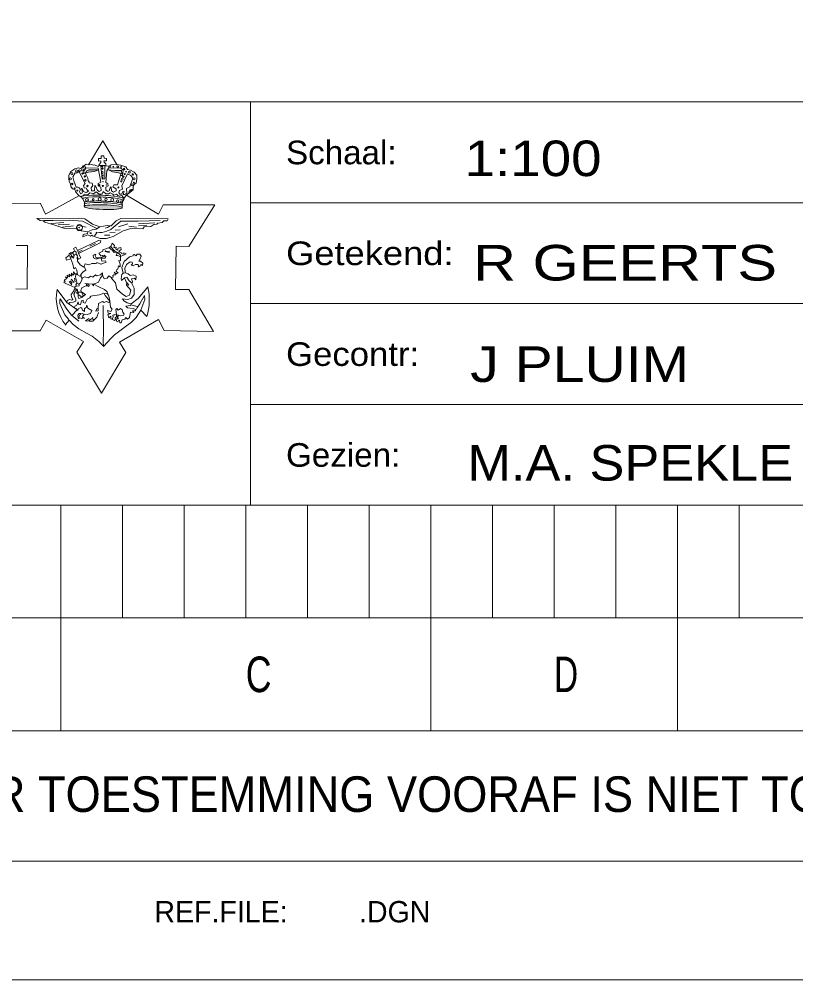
# Model space of a CAD drawing. Extents: x 295824 to 414724, y 24924 to 109024.
# Drawn here: x 402973 to 409522, y 24924 to 33022 of the extents above; entities that cross this region are included whole.
import ezdxf

# ---------------------------------------------------------------- set-up
doc = ezdxf.new("R2010")
doc.units = 0
doc.header["$LTSCALE"] = 100
doc.header["$PDMODE"] = 32
doc.header["$PDSIZE"] = 50
doc.layers.add('1', color=7, linetype='Continuous', lineweight=13)
doc.layers.add('3', color=7, linetype='Continuous')

msp = doc.modelspace()

# ---------------------------------------------------------------- hatches: boundary and pattern name
at = {"layer": '1'}
for points in [[(403531.6, 31722.8), (403540.6, 31743.8), (403560.6, 31751.8), (403641.6, 31751.8), (403609.6, 31737.8), (403557.6, 31731.8)], [(403720.6, 31751.8), (403780.6, 31745.8), (403834.6, 31745.8), (403837.6, 31716.8), (403809.6, 31727.8), (403760.6, 31733.8), (403725.6, 31750.8)]]:
    msp.add_hatch(color=256, dxfattribs=at).paths.add_polyline_path(points)
h = msp.add_hatch(color=256, dxfattribs=at)
edge = h.paths.add_edge_path()
edge.add_ellipse((403681.3, 31437.6), major_axis=(161, -5), ratio=0.122443, start_angle=0, end_angle=360)

# ---------------------------------------------------------------- linework, layer by layer
for p, q in [((395823.6, 32323.8), (413723.6, 32323.8)), ((404923.6, 32323.8), (404923.6, 28923.8)), ((403696.6, 31787.8), (403649.6, 31787.8)), ((403662.6, 31785.8), (403672.6, 31673.8)), ((403475.6, 31533.8), (403195.6, 31378.8)), ((403494.6, 31523.8), (403508.6, 31507.8)), ((403857.6, 31507.8), (403849.6, 31493.8)), ((403877.6, 31538.8), (404148.6, 31377.8)), ((403520.6, 31443.8), (403522.6, 31463.8)), ((403841.6, 31432.8), (403841.6, 31453.8)), ((404923.6, 31473.8), (413723.6, 31473.8)), ((403180.6, 31324.8), (403259.6, 31324.8)), ((403242.6, 31298.8), (403348.6, 31308.8)), ((403300.6, 31288.8), (403398.6, 31294.8)), ((403338.6, 31269.8), (403431.6, 31279.8)), ((403453.6, 31258.8), (403481.6, 31264.8)), ((403471.6, 31282.8), (403536.6, 31269.8)), ((403506.6, 31317.8), (403628.6, 31257.8)), ((403811.6, 31271.8), (403890.6, 31295.8)), ((403896.6, 31275.8), (403961.6, 31268.8)), ((403976.6, 31319.8), (404161.6, 31325.8)), ((403979.6, 31297.8), (404117.6, 31304.8)), ((403980.6, 31279.8), (404049.6, 31285.8)), ((403693.6, 31199.8), (403737.6, 31200.8)), ((403737.6, 31222.8), (403781.6, 31219.8)), ((403781.6, 31243.8), (403825.6, 31244.8)), ((403568.6, 31108.8), (403615.6, 31129.8)), ((403391.6, 31027.8), (403410.6, 31016.8)), ((403412.6, 31018.8), (403432.6, 31026.8)), ((403466.6, 31069.8), (403474.6, 31046.8)), ((403473.6, 31057.8), (403503.6, 31074.8)), ((403679.6, 31024.8), (403696.6, 31017.8)), ((403394.6, 30811.8), (403417.6, 30781.8)), ((403404.6, 30816.8), (403420.6, 30797.8)), ((403412.6, 30830.8), (403437.6, 30801.8)), ((403439.6, 30839.8), (403445.6, 30808.8)), ((403914.6, 30613.8), (403967.6, 30598.8)), ((404923.6, 30623.8), (413723.6, 30623.8)), ((403522.6, 30498.8), (403507.6, 30512.8)), ((403588.6, 30498.8), (403594.6, 30509.8)), ((404923.6, 29773.8), (413723.6, 29773.8)), ((395823.6, 28923.8), (413723.6, 28923.8)), ((403323.6, 28923.8), (403323.6, 27023.8)), ((403843.6, 28923.8), (403843.6, 27973.8)), ((404363.6, 28923.8), (404363.6, 27973.8)), ((404883.6, 28923.8), (404883.6, 27973.8)), ((405403.6, 28923.8), (405403.6, 27973.8)), ((405923.6, 28923.8), (405923.6, 27973.8)), ((406443.6, 28923.8), (406443.6, 27023.8)), ((406963.6, 28923.8), (406963.6, 27973.8)), ((407483.6, 28923.8), (407483.6, 27973.8)), ((408003.6, 28923.8), (408003.6, 27973.8)), ((408523.6, 28923.8), (408523.6, 27023.8)), ((409043.6, 28923.8), (409043.6, 27973.8)), ((413723.6, 27973.8), (399163.6, 27973.8)), ((395823.6, 27023.8), (413723.6, 27023.8)), ((304995.6, 24923.8), (414723.6, 24923.8))]:
    msp.add_line(p, q, dxfattribs=at)
for points in [[(304995.6, 25923.8), (413723.6, 25923.8), (413723.6, 108023.8), (304995.6, 108023.8)], [(403557.6, 31794.8), (403678.6, 31996.8), (403795.6, 31795.8)], [(403493.6, 31524.8), (403475.6, 31536.8), (403449.6, 31562.8), (403441.6, 31584.8), (403423.6, 31592.8), (403407.6, 31610.8), (403404.6, 31632.8), (403394.6, 31653.8), (403390.6, 31675.8), (403391.6, 31707.8), (403408.6, 31737.8), (403441.6, 31760.8), (403472.6, 31768.8), (403489.6, 31763.8), (403504.6, 31771.8), (403512.6, 31786.8), (403524.6, 31787.8), (403538.6, 31798.8), (403556.6, 31793.8), (403585.6, 31796.8), (403595.6, 31789.8), (403606.6, 31792.8), (403642.6, 31780.8), (403647.6, 31796.8), (403660.6, 31814.8), (403660.6, 31826.8), (403641.6, 31825.8), (403642.6, 31846.8), (403663.6, 31847.8), (403663.6, 31869.8), (403687.6, 31869.8), (403690.6, 31849.8), (403709.6, 31848.8), (403709.6, 31827.8), (403687.6, 31827.8), (403689.6, 31816.8), (403703.6, 31801.8), (403704.6, 31786.8), (403732.6, 31781.8), (403747.6, 31793.8)], [(403608.6, 31575.8), (403611.6, 31618.8), (403616.6, 31616.8), (403633.6, 31576.8), (403647.6, 31568.8), (403664.6, 31576.8), (403660.6, 31604.8), (403639.6, 31615.8), (403639.6, 31636.8), (403654.6, 31644.8), (403662.6, 31648.8), (403638.6, 31764.8), (403538.6, 31769.8), (403517.6, 31743.8), (403518.6, 31720.8), (403530.6, 31725.8), (403551.6, 31680.8), (403555.6, 31659.8), (403563.6, 31649.8), (403562.6, 31641.8), (403589.6, 31640.8), (403594.6, 31619.8), (403579.6, 31599.8), (403583.6, 31574.8), (403608.6, 31574.8)], [(403672.6, 31671.8), (403694.6, 31675.8), (403695.6, 31785.8), (403702.6, 31786.8)], [(403827.6, 31702.8), (403844.6, 31704.8), (403850.6, 31749.8), (403831.6, 31764.8), (403792.6, 31768.8), (403726.6, 31766.8), (403711.6, 31742.8), (403703.6, 31644.8), (403720.6, 31634.8), (403722.6, 31615.8), (403702.6, 31605.8), (403702.6, 31579.8), (403718.6, 31570.8)], [(403747.6, 31793.8), (403791.6, 31796.8), (403830.6, 31790.8)], [(403827.6, 31791.8), (403871.6, 31775.8), (403887.6, 31755.8), (403910.6, 31749.8), (403943.6, 31730.8), (403966.6, 31706.8), (403964.6, 31675.8), (403959.6, 31638.8), (403941.6, 31628.8), (403935.6, 31607.8), (403935.6, 31583.8), (403884.6, 31542.8), (403854.6, 31511.8)], [(403542.6, 31562.8), (403556.6, 31572.8), (403543.6, 31584.8), (403540.6, 31596.8), (403521.6, 31598.8), (403515.6, 31619.8), (403529.6, 31635.8), (403478.6, 31735.8), (403457.6, 31723.8), (403444.6, 31725.8), (403426.6, 31693.8), (403432.6, 31657.8), (403453.6, 31605.8), (403466.6, 31605.8), (403478.6, 31598.8), (403490.6, 31586.8), (403481.6, 31567.8), (403490.6, 31549.8), (403501.6, 31552.8), (403506.6, 31564.8), (403498.6, 31594.8), (403505.6, 31595.8), (403516.6, 31568.8), (403535.6, 31559.8), (403539.6, 31560.8)], [(403718.6, 31568.8), (403730.6, 31574.8), (403742.6, 31609.8), (403748.6, 31606.8), (403750.6, 31573.8), (403767.6, 31564.8), (403789.6, 31573.8), (403791.6, 31591.8), (403763.6, 31607.8), (403771.6, 31624.8), (403802.6, 31624.8), (403831.6, 31715.8)], [(403834.6, 31545.8), (403849.6, 31570.8), (403858.6, 31567.8), (403848.6, 31543.8), (403864.6, 31543.8), (403879.6, 31553.8), (403877.6, 31595.8), (403906.6, 31609.8), (403932.6, 31682.8), (403915.6, 31704.8), (403887.6, 31717.8), (403860.6, 31663.8), (403838.6, 31617.8), (403844.6, 31587.8), (403819.6, 31577.8), (403813.6, 31556.8), (403822.6, 31545.8), (403836.6, 31546.8)], [(403494.6, 31523.8), (403493.6, 31526.8), (403517.6, 31538.8), (403520.6, 31547.8), (403540.6, 31541.8), (403554.6, 31544.8), (403567.6, 31557.8), (403599.6, 31550.8), (403621.6, 31566.8), (403646.6, 31547.8), (403661.6, 31546.8), (403673.6, 31550.8), (403682.6, 31568.8), (403704.6, 31549.8), (403725.6, 31549.8), (403740.6, 31558.8), (403761.6, 31546.8), (403770.6, 31538.8), (403794.6, 31547.8), (403804.6, 31535.8), (403817.6, 31528.8), (403837.6, 31535.8), (403850.6, 31521.8), (403858.6, 31509.8)], [(403508.6, 31507.8), (403524.6, 31476.8), (403522.6, 31464.8)], [(402734.6, 30393.8), (403150.6, 30395.8), (403201.6, 30485.8), (403514.6, 30304.8), (403458.6, 30213.8), (403668.6, 29867.8), (403871.6, 30212.8), (403818.6, 30299.8), (404148.6, 30489.8), (404195.6, 30398.8), (404610.6, 30388.8), (404402.6, 30743.8), (404291.6, 30741.8), (404295.6, 31108.8), (404404.6, 31104.8), (404622.6, 31456.8), (404188.6, 31456.8), (404148.6, 31377.8)], [(403195.6, 31378.8), (403153.6, 31468.8), (402745.6, 31469.8)], [(403849.6, 31493.8), (403842.6, 31466.8), (403843.6, 31450.8)], [(403652.6, 31271.8), (403592.6, 31292.8), (403525.6, 31339.8), (403475.6, 31343.8), (403121.6, 31342.8), (403149.6, 31325.8), (403175.6, 31322.8), (403189.6, 31309.8), (403266.6, 31287.8), (403350.6, 31260.8), (403455.6, 31257.8), (403477.6, 31241.8), (403488.6, 31244.8), (403499.6, 31238.8), (403551.6, 31228.8), (403548.6, 31214.8), (403511.6, 31207.8), (403509.6, 31187.8), (403551.6, 31203.8)], [(403654.6, 31171.8), (403709.6, 31171.8), (403764.6, 31190.8), (403849.6, 31238.8), (403914.6, 31257.8), (404016.6, 31254.8), (404027.6, 31271.8), (404083.6, 31274.8), (404109.6, 31291.8), (404134.6, 31292.8), (404141.6, 31302.8), (404178.6, 31306.8), (404191.6, 31321.8), (404220.6, 31322.8), (404228.6, 31338.8), (403830.6, 31341.8), (403791.6, 31321.8), (403748.6, 31279.8), (403714.6, 31281.8), (403652.6, 31271.8), (403622.6, 31251.8), (403588.6, 31244.8), (403562.6, 31234.8), (403549.6, 31228.8)], [(403259.6, 31324.8), (403398.6, 31326.8), (403506.6, 31317.8)], [(403607.6, 31195.8), (403618.6, 31208.8), (403624.6, 31218.8), (403621.6, 31226.8), (403649.6, 31222.8), (403673.6, 31223.8), (403712.6, 31233.8), (403744.6, 31249.8), (403764.6, 31266.8)], [(403698.6, 31258.8), (403716.6, 31265.8), (403739.6, 31280.8)], [(403764.6, 31266.8), (403829.6, 31319.8), (403976.6, 31319.8)], [(403551.6, 31203.8), (403575.6, 31193.8), (403584.6, 31200.8), (403592.6, 31194.8), (403631.6, 31180.8), (403654.6, 31171.8)], [(403568.6, 31222.8), (403586.6, 31217.8), (403577.6, 31214.8), (403569.6, 31220.8)], [(402947.6, 31114.8), (403044.6, 31112.8), (403040.6, 30746.8), (402944.6, 30749.8)], [(403493.6, 30861.8), (403483.6, 30856.8), (403464.6, 30866.8), (403459.6, 30905.8), (403446.6, 30928.8), (403432.6, 30917.8), (403426.6, 30957.8), (403408.6, 31000.8), (403372.6, 30989.8), (403365.6, 31008.8), (403395.6, 31031.8), (403394.6, 31043.8), (403406.6, 31050.8), (403427.6, 31056.8), (403432.6, 31063.8), (403441.6, 31066.8), (403431.6, 31089.8), (403450.6, 31098.8), (403465.6, 31070.8), (403642.6, 31155.8), (403660.6, 31152.8), (403654.6, 31137.8), (403474.6, 31046.8), (403493.6, 31010.8), (403474.6, 30999.8), (403462.6, 31014.8), (403464.6, 31027.8), (403454.6, 31040.8), (403454.6, 31057.8), (403440.6, 31068.8)], [(403661.6, 30955.8), (403705.6, 30974.8), (403700.6, 30984.8), (403669.6, 30981.8), (403665.6, 31005.8), (403697.6, 31007.8), (403702.6, 31021.8), (403688.6, 31033.8), (403660.6, 31027.8), (403644.6, 31048.8), (403677.6, 31066.8), (403679.6, 31076.8), (403733.6, 31097.8), (403747.6, 31109.8), (403757.6, 31134.8), (403775.6, 31113.8), (403771.6, 31097.8), (403779.6, 31096.8), (403790.6, 31099.8), (403787.6, 31084.8), (403801.6, 31074.8), (403806.6, 31090.8), (403830.6, 31097.8), (403832.6, 31079.8), (403814.6, 31064.8), (403820.6, 31056.8), (403832.6, 31054.8), (403832.6, 31048.8), (403848.6, 31041.8), (403855.6, 31052.8), (403876.6, 31043.8), (403851.6, 31032.8), (403827.6, 31020.8), (403827.6, 30998.8), (403827.6, 30984.8), (403814.6, 30987.8), (403824.6, 30957.8), (403823.6, 30933.8), (403810.6, 30941.8), (403804.6, 30915.8)], [(403745.6, 31103.8), (403782.6, 31063.8), (403804.6, 31053.8), (403826.6, 31031.8), (403827.6, 31024.8)], [(403453.6, 31041.8), (403436.6, 31033.8), (403430.6, 31007.8), (403415.6, 31020.8), (403403.6, 31014.8), (403409.6, 31001.8)], [(403410.6, 31019.8), (403415.6, 31030.8), (403405.6, 31043.8), (403422.6, 31051.8), (403434.6, 31034.8)], [(403519.6, 30930.8), (403488.6, 30949.8), (403464.6, 30980.8), (403462.6, 31014.8)], [(403667.6, 31003.8), (403658.6, 31008.8), (403623.6, 30997.8), (403599.6, 31008.8), (403597.6, 31033.8), (403619.6, 31041.8), (403612.6, 31026.8), (403623.6, 31009.8), (403653.6, 31010.8), (403679.6, 31019.8), (403676.6, 31029.8)], [(403701.6, 31069.8), (403713.6, 31063.8), (403730.6, 31064.8), (403730.6, 31055.8), (403717.6, 31056.8), (403697.6, 31062.8), (403700.6, 31070.8)], [(403732.6, 31094.8), (403757.6, 31074.8), (403773.6, 31053.8), (403792.6, 31058.8), (403800.6, 31049.8), (403790.6, 31029.8), (403801.6, 31029.8), (403825.6, 31020.8)], [(403871.6, 30883.8), (403849.6, 30880.8), (403839.6, 30928.8), (403857.6, 30979.8), (403903.6, 31017.8), (403935.6, 31027.8), (403933.6, 31034.8), (403943.6, 31038.8), (403959.6, 31027.8), (403965.6, 31035.8), (403964.6, 31041.8), (403990.6, 31041.8), (404001.6, 31023.8), (403992.6, 31000.8), (403982.6, 30980.8), (403995.6, 30982.8), (404015.6, 30963.8), (404012.6, 30944.8), (403998.6, 30954.8), (403990.6, 30937.8), (403977.6, 30932.8), (403982.6, 30943.8), (403973.6, 30954.8), (403954.6, 30952.8), (403935.6, 30941.8), (403916.6, 30947.8), (403929.6, 30958.8), (403924.6, 30973.8), (403907.6, 30975.8), (403878.6, 30954.8), (403864.6, 30922.8), (403865.6, 30891.8), (403870.6, 30883.8)], [(403804.6, 30915.8), (403792.6, 30908.8), (403791.6, 30897.8), (403799.6, 30888.8), (403808.6, 30886.8), (403794.6, 30874.8), (403787.6, 30877.8), (403774.6, 30887.8), (403782.6, 30876.8), (403786.6, 30865.8), (403771.6, 30867.8), (403762.6, 30859.8), (403766.6, 30845.8), (403747.6, 30844.8), (403728.6, 30858.8), (403714.6, 30837.8), (403688.6, 30833.8), (403676.6, 30862.8), (403674.6, 30884.8), (403658.6, 30866.8), (403625.6, 30858.8), (403617.6, 30865.8), (403594.6, 30846.8), (403576.6, 30856.8), (403555.6, 30841.8), (403525.6, 30849.8), (403497.6, 30839.8), (403493.6, 30869.8), (403512.6, 30892.8), (403534.6, 30906.8), (403520.6, 30935.8), (403529.6, 30960.8), (403561.6, 30951.8), (403585.6, 30962.8), (403617.6, 30961.8), (403628.6, 30963.8), (403628.6, 30970.8), (403663.6, 30955.8)], [(403461.6, 30794.8), (403447.6, 30848.8), (403449.6, 30867.8), (403458.6, 30874.8), (403441.6, 30874.8), (403431.6, 30890.8), (403433.6, 30871.8), (403425.6, 30863.8), (403413.6, 30881.8), (403415.6, 30856.8), (403394.6, 30871.8), (403396.6, 30850.8), (403377.6, 30863.8), (403379.6, 30840.8), (403363.6, 30848.8), (403373.6, 30831.8), (403353.6, 30823.8), (403360.6, 30810.8), (403348.6, 30800.8), (403367.6, 30793.8), (403441.6, 30760.8)], [(403531.6, 30701.8), (403509.6, 30683.8), (403500.6, 30676.8), (403475.6, 30666.8), (403470.6, 30678.8), (403469.6, 30701.8), (403491.6, 30687.8), (403493.6, 30680.8), (403506.6, 30682.8), (403512.6, 30693.8), (403491.6, 30735.8), (403502.6, 30755.8), (403528.6, 30769.8), (403548.6, 30772.8), (403560.6, 30767.8), (403563.6, 30775.8), (403554.6, 30785.8), (403541.6, 30773.8), (403540.6, 30789.8), (403526.6, 30793.8), (403592.6, 30786.8), (403598.6, 30774.8), (403602.6, 30789.8), (403616.6, 30793.8), (403640.6, 30803.8), (403657.6, 30840.8), (403678.6, 30863.8)], [(403748.6, 30844.8), (403759.6, 30827.8), (403785.6, 30799.8), (403797.6, 30745.8), (403844.6, 30703.8), (403875.6, 30682.8), (403904.6, 30694.8), (403913.6, 30737.8), (403877.6, 30780.8), (403877.6, 30790.8), (403898.6, 30780.8), (403874.6, 30807.8), (403861.6, 30840.8), (403836.6, 30818.8), (403832.6, 30836.8), (403839.6, 30869.8), (403850.6, 30881.8)], [(403872.6, 30884.8), (403892.6, 30875.8), (403908.6, 30860.8), (403934.6, 30867.8), (403959.6, 30855.8), (403955.6, 30824.8), (403944.6, 30838.8), (403921.6, 30833.8), (403928.6, 30809.8), (403924.6, 30796.8), (403901.6, 30814.8), (403880.6, 30845.8), (403860.6, 30841.8)], [(403506.6, 30841.8), (403498.6, 30815.8), (403488.6, 30795.8), (403475.6, 30785.8), (403478.6, 30774.8), (403454.6, 30771.8), (403441.6, 30761.8), (403442.6, 30747.8), (403445.6, 30744.8), (403437.6, 30744.8), (403433.6, 30732.8), (403437.6, 30728.8), (403427.6, 30722.8), (403411.6, 30699.8), (403414.6, 30678.8), (403426.6, 30658.8), (403416.6, 30653.8), (403397.6, 30658.8), (403377.6, 30649.8), (403375.6, 30632.8), (403392.6, 30623.8), (403399.6, 30632.8), (403429.6, 30635.8), (403449.6, 30643.8), (403451.6, 30662.8), (403439.6, 30685.8), (403433.6, 30703.8), (403443.6, 30717.8), (403444.6, 30727.8), (403452.6, 30733.8), (403459.6, 30740.8), (403446.6, 30748.8), (403461.6, 30744.8), (403466.6, 30726.8), (403456.6, 30719.8), (403465.6, 30705.8), (403474.6, 30708.8), (403468.6, 30721.8), (403501.6, 30720.8), (403531.6, 30701.8)], [(403477.6, 30788.8), (403460.6, 30795.8), (403450.6, 30781.8), (403452.6, 30773.8)], [(403603.6, 30787.8), (403644.6, 30766.8), (403692.6, 30741.8), (403715.6, 30722.8), (403716.6, 30708.8), (403687.6, 30711.8), (403649.6, 30696.8), (403591.6, 30688.8), (403576.6, 30685.8), (403567.6, 30671.8)], [(403922.6, 30794.8), (403942.6, 30754.8), (403942.6, 30699.8), (403921.6, 30669.8), (403889.6, 30659.8), (403844.6, 30664.8), (403855.6, 30648.8), (403882.6, 30629.8), (403917.6, 30622.8), (403975.6, 30666.8), (404034.6, 30736.8), (404058.6, 30765.8)], [(403416.6, 30522.8), (403462.6, 30570.8), (403374.6, 30632.8), (403292.6, 30741.8)], [(403689.6, 30709.8), (403698.6, 30691.8), (403737.6, 30644.8), (403728.6, 30632.8), (403707.6, 30641.8), (403688.6, 30633.8), (403676.6, 30640.8), (403640.6, 30624.8), (403639.6, 30590.8), (403639.6, 30561.8), (403618.6, 30559.8), (403631.6, 30586.8)], [(403715.6, 30708.8), (403726.6, 30694.8), (403733.6, 30664.8), (403738.6, 30643.8)], [(404049.6, 30516.8), (403999.6, 30569.8), (404032.6, 30659.8), (404029.6, 30692.8), (403990.6, 30622.8), (403969.6, 30594.8), (403958.6, 30574.8)], [(403475.6, 30475.8), (403413.6, 30526.8), (403375.6, 30576.8), (403319.6, 30664.8), (403315.6, 30659.8), (403316.6, 30623.8), (403334.6, 30580.8), (403357.6, 30530.8), (403390.6, 30488.8)], [(403567.6, 30672.8), (403547.6, 30662.8), (403528.6, 30627.8), (403512.6, 30634.8), (403513.6, 30651.8), (403498.6, 30647.8), (403489.6, 30612.8), (403474.6, 30619.8), (403470.6, 30639.8), (403460.6, 30609.8), (403442.6, 30602.8), (403438.6, 30586.8), (403450.6, 30583.8), (403466.6, 30564.8), (403471.6, 30580.8), (403492.6, 30590.8), (403502.6, 30585.8), (403506.6, 30569.8), (403524.6, 30556.8), (403524.6, 30581.8), (403537.6, 30591.8), (403543.6, 30609.8), (403550.6, 30585.8), (403586.6, 30564.8), (403575.6, 30540.8), (403545.6, 30532.8), (403520.6, 30535.8), (403506.6, 30514.8)], [(403753.6, 30492.8), (403744.6, 30496.8), (403745.6, 30518.8), (403729.6, 30503.8), (403720.6, 30531.8), (403745.6, 30539.8), (403723.6, 30542.8), (403718.6, 30564.8), (403746.6, 30557.8), (403756.6, 30576.8), (403742.6, 30593.8), (403737.6, 30643.8)], [(403917.6, 30621.8), (403915.6, 30616.8), (403912.6, 30608.8), (403872.6, 30603.8), (403887.6, 30587.8), (403935.6, 30582.8), (403953.6, 30573.8), (403953.6, 30562.8), (403929.6, 30561.8), (403940.6, 30548.8), (403912.6, 30552.8), (403902.6, 30506.8), (403887.6, 30492.8), (403872.6, 30505.8), (403863.6, 30492.8), (403842.6, 30486.8), (403833.6, 30462.8), (403822.6, 30462.8), (403819.6, 30483.8), (403811.6, 30481.8), (403804.6, 30470.8), (403794.6, 30475.8), (403789.6, 30494.8), (403810.6, 30494.8), (403800.6, 30511.8), (403793.6, 30513.8), (403782.6, 30503.8), (403786.6, 30490.8), (403775.6, 30482.8), (403760.6, 30489.8), (403758.6, 30497.8), (403766.6, 30512.8)], [(403492.6, 30539.8), (403477.6, 30540.8), (403466.6, 30527.8), (403471.6, 30502.8)], [(403475.6, 30508.8), (403485.6, 30528.8), (403505.6, 30539.8), (403515.6, 30535.8)], [(403641.6, 30548.8), (403628.6, 30509.8), (403593.6, 30476.8), (403564.6, 30474.8), (403566.6, 30483.8), (403582.6, 30495.8), (403592.6, 30496.8), (403600.6, 30490.8)], [(403999.6, 30569.8), (403960.6, 30506.8), (403921.6, 30467.8), (403855.6, 30418.8), (403777.6, 30361.8), (403748.6, 30332.8), (403684.6, 30263.8), (403682.6, 30308.8), (403684.6, 30379.8), (403682.6, 30607.8)], [(403766.6, 30511.8), (403763.6, 30526.8), (403770.6, 30530.8), (403780.6, 30529.8), (403793.6, 30531.8), (403788.6, 30574.8), (403795.6, 30583.8), (403806.6, 30568.8), (403826.6, 30583.8), (403841.6, 30572.8), (403847.6, 30550.8), (403858.6, 30533.8), (403853.6, 30522.8), (403829.6, 30519.8), (403811.6, 30527.8), (403796.6, 30527.8), (403791.6, 30519.8), (403808.6, 30515.8), (403810.6, 30522.8)], [(403362.6, 30447.8), (403393.6, 30484.8), (403429.6, 30447.8), (403476.6, 30411.8), (403547.6, 30371.8), (403589.6, 30350.8), (403644.6, 30305.8), (403686.6, 30261.8)], [(403511.6, 30505.8), (403501.6, 30497.8), (403480.6, 30502.8), (403470.6, 30495.8)], [(403560.6, 30480.8), (403548.6, 30474.8), (403532.6, 30477.8), (403561.6, 30499.8), (403564.6, 30491.8)]]:
    msp.add_lwpolyline(points, dxfattribs=at)
for points in [[(395823.6, 25923.8), (413723.6, 25923.8), (413723.6, 38123.8), (395823.6, 38123.8)], [(403531.6, 31722.8), (403540.6, 31743.8), (403560.6, 31751.8), (403641.6, 31751.8), (403609.6, 31737.8), (403557.6, 31731.8)], [(403720.6, 31751.8), (403780.6, 31745.8), (403834.6, 31745.8), (403837.6, 31716.8), (403809.6, 31727.8), (403760.6, 31733.8), (403725.6, 31750.8)]]:
    msp.add_lwpolyline(points, close=True, dxfattribs=at)
for centre, radius in [((403456.3, 31742.6), 9.06), ((403480.3, 31744.6), 8), ((403506.3, 31750.6), 8.54), ((403524.3, 31774.6), 9.22), ((403672.3, 31783.6), 6), ((403675.3, 31762.6), 5.39), ((403735.3, 31776.6), 7.28), ((403767.3, 31778.6), 3.16), ((403804.3, 31778.6), 7.28), ((403832.3, 31776.6), 3.16), ((403858.3, 31758.6), 6), ((403405.3, 31675.6), 9.22), ((403417.3, 31718.6), 9.49), ((403507.3, 31720.6), 5), ((403527.3, 31696.6), 5.39), ((403531.3, 31663.6), 7), ((403674.3, 31728.6), 7.81), ((403676.3, 31683.6), 4.47), ((403677.3, 31703.6), 5), ((403842.3, 31673.6), 8.06), ((403851.3, 31694.6), 6.08), ((403863.3, 31716.6), 4), ((403873.3, 31736.6), 3.16), ((403901.3, 31731.6), 9.06), ((403931.3, 31712.6), 6), ((403942.3, 31675.6), 8), ((403420.3, 31632.6), 6.32), ((403440.3, 31595.6), 4), ((403548.3, 31615.6), 6.08), ((403649.3, 31623.6), 4), ((403678.3, 31615.6), 5.39), ((403680.3, 31652.6), 1.41), ((403708.3, 31624.6), 1.41), ((403809.3, 31603.6), 4.12), ((403834.3, 31653.6), 4.12), ((403907.3, 31578.6), 3), ((403920.3, 31580.6), 6.08), ((403926.3, 31624.6), 8.25), ((403940.3, 31643.6), 4.12), ((403463.3, 31576.6), 4.12), ((403544.3, 31498.6), 12), ((403597.3, 31502.6), 7.28), ((403652.3, 31504.6), 13.2), ((403706.3, 31502.6), 10.1), ((403757.3, 31497.6), 12), ((403903.3, 31563.6), 4.24), ((403803.3, 31488.6), 10.8), ((403832.3, 31482.6), 8.54)]:
    msp.add_circle(centre, radius, dxfattribs=at)
for centre, radius, start, end in [((403659.3, 30673.6), 373.3, 169.49737, 218.03161), ((403573.1, 30656.6), 497.4, 343.65538, 12.66423)]:
    msp.add_arc(centre, radius, start, end, dxfattribs=at)
for centre, major_axis, ratio in [((403675.3, 31515.1), (182, -7.5), 0.12032), ((403679.3, 31499.6), (171, -8), 0.131533), ((403682.8, 31457.1), (160.5, -6.5), 0.111744), ((403683.8, 31470.6), (159.5, -6), 0.111275)]:
    msp.add_ellipse(centre, major_axis=major_axis, ratio=ratio, start_param=6.283185, end_param=9.424778, dxfattribs=at)
msp.add_ellipse((403681.3, 31437.6), major_axis=(161, -5), ratio=0.122443, dxfattribs=at)
msp.add_point((403481.6, 31264.8), dxfattribs=at)

# ---------------------------------------------------------------- texts
for s, height, width, p in [('Schaal:', 199, 1.05, (405223.6, 31798.8)), ('Getekend:', 199, 1.15, (405223.6, 30948.8)), ('Gecontr:', 199, 1.1, (405223.6, 30098.8)), ('Gezien:', 199, 1.05, (405223.6, 29248.8)), ('C', 300, 0.75, (404883.6, 27348.8)), ('D', 300, 0.7, (407483.6, 27348.8)), ('REPRODUCEREN ZONDER TOESTEMMING VOORAF IS NIET TOEGESTAAN', 300, 0.95, (398070.6, 26338.8))]:
    msp.add_text(s, height=height, dxfattribs=dict(at, width=width)).set_placement(p)
msp.add_text('REF.FILE:         .DGN', height=180, dxfattribs=at).set_placement((404113.6, 25407.8))
at = {"layer": '3'}
for s, width, p in [('1:100            ', 1.15, (406729.6, 31698.8)), ('R GEERTS         ', 1.25, (406800.6, 30818.8)), ('J PLUIM          ', 1.2, (406776.6, 29963.8)), ('M.A. SPEKLE      ', 1.1, (406752.6, 29131.8))]:
    msp.add_text(s, height=300, dxfattribs=dict(at, width=width)).set_placement(p)

doc.saveas('drawing.dxf')
